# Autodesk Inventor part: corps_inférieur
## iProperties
Author: David YERLE
Shininess: 64.0
Length Units: 11269
Angle Units: 11279
Time Units: 11290
Mass Units: 11283
Length Display Precision: 3
Angle Display Precision: 2
Compacted: True
Part Number: corps_inférieur
Document SubType Name: Modeling
Created: 2004-05
Material: Par défaut
Designer: David
Density: 0.0
Volumn: 0.0
Area: 0.0
PropertySet Name: Model Information
Control State: 0
Master: False
Checked Out: False
Author: David
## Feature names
1. Lissage1
2. Dépouille de face1
3. Congé1 [Fillet]
4. Extrusion3
5. Congé5 [Fillet]
6. Coque1
7. Extrusion4
8. Extrusion5
9. Extrusion7
10. Extrusion8
11. Extrusion9
12. Extrusion10
13. Symétrie2 [Mirror]
14. Extrusion11
15. Extrusion12
16. Extrusion13
17. Extrusion14
18. Extrusion15
19. Extrusion16
20. Extrusion18
21. Extrusion19
22. Extrusion20
23. Congé6 [Fillet]
24. Extrusion21
25. Extrusion22
26. Extrusion23
27. Extrusion24
28. Extrusion25
29. Extrusion31
30. Extrusion32
31. Extrusion33
32. Extrusion34
33. Extrusion35
34. Extrusion36
35. Extrusion37
36. Perçage1 [Hole]
37. Symétrie3 [Mirror]
38. Extrusion38
39. Extrusion39
40. Symétrie4 [Mirror]
41. Extrusion40
42. Extrusion41
